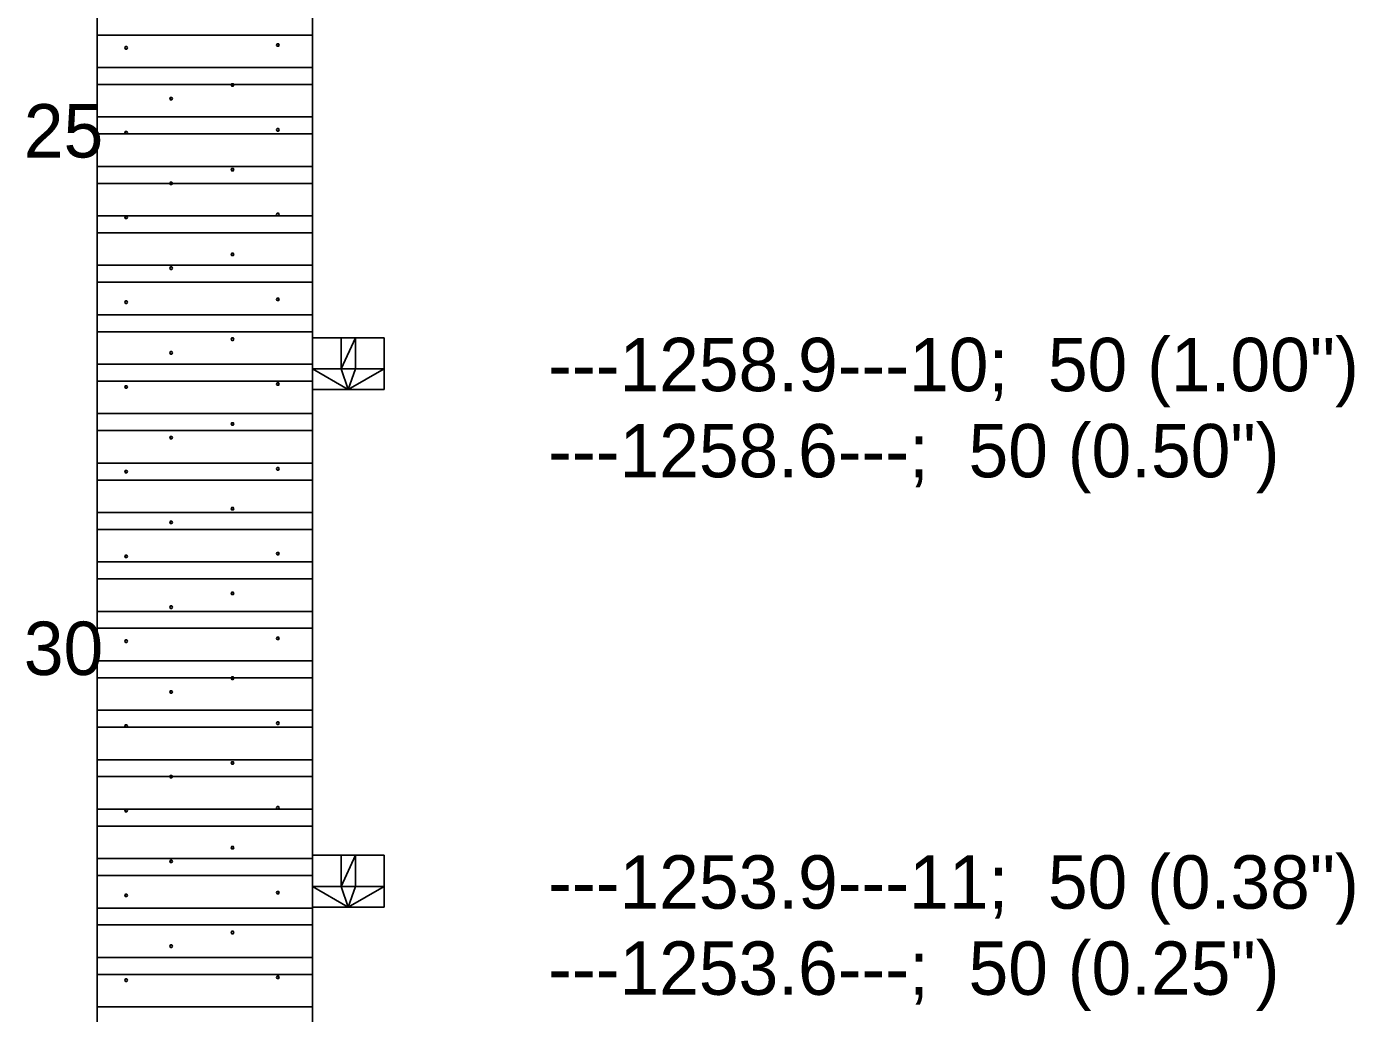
# Model space of a CAD drawing. Extents: x 2150148.6 to 2150220.1, y 143803.7 to 143875.1.
# Drawn here: x 2150191.796 to 2150194.882, y 143819.958 to 143822.25 of the extents above; entities that cross this region are included whole.
import ezdxf

# ---------------------------------------------------------------- set-up
doc = ezdxf.new("R2010")
doc.units = 0
doc.layers.add('Default', color=7, linetype='Continuous')

msp = doc.modelspace()

# ---------------------------------------------------------------- linework, layer by layer
at = {"layer": 'Default'}
for points in [[(2150191.9604, 143828.0174), (2150191.9604, 143817.9213)], [(2150192.4604, 143828.0174), (2150192.4604, 143817.9213)], [(2150191.9604, 143822.2303), (2150192.4604, 143822.2303)], [(2150192.0308, 143822.2005), (2150192.0292, 143822.2033), (2150192.0259, 143822.2033), (2150192.0243, 143822.2005), (2150192.0259, 143822.1976), (2150192.0292, 143822.1976), (2150192.0308, 143822.2005)], [(2150192.3836, 143822.207), (2150192.3819, 143822.2099), (2150192.3787, 143822.2099), (2150192.377, 143822.207), (2150192.3787, 143822.2041), (2150192.3819, 143822.2041), (2150192.3836, 143822.207)], [(2150191.9604, 143822.1548), (2150192.4604, 143822.1548)], [(2150191.9604, 143822.1154), (2150192.4604, 143822.1154)], [(2150192.2781, 143822.1144), (2150192.2764, 143822.1173), (2150192.2731, 143822.1173), (2150192.2715, 143822.1144), (2150192.2731, 143822.1116), (2150192.2764, 143822.1116), (2150192.2781, 143822.1144)], [(2150192.1355, 143822.0826), (2150192.1338, 143822.0854), (2150192.1306, 143822.0854), (2150192.1289, 143822.0826), (2150192.1306, 143822.0797), (2150192.1338, 143822.0797), (2150192.1355, 143822.0826)], [(2150191.9604, 143822.04), (2150192.4604, 143822.04)], [(2150192.0308, 143822.0036), (2150192.0292, 143822.0064), (2150192.0259, 143822.0064), (2150192.0243, 143822.0036), (2150192.0259, 143822.0007), (2150192.0292, 143822.0007), (2150192.0308, 143822.0036)], [(2150192.3836, 143822.0101), (2150192.3819, 143822.013), (2150192.3787, 143822.013), (2150192.377, 143822.0101), (2150192.3787, 143822.0073), (2150192.3819, 143822.0073), (2150192.3836, 143822.0101)], [(2150191.9604, 143822.0006), (2150192.4604, 143822.0006)], [(2150191.9604, 143821.9251), (2150192.4604, 143821.9251)], [(2150192.2781, 143821.9176), (2150192.2764, 143821.9204), (2150192.2731, 143821.9204), (2150192.2715, 143821.9176), (2150192.2731, 143821.9148), (2150192.2764, 143821.9148), (2150192.2781, 143821.9176)], [(2150191.9604, 143821.8858), (2150192.4604, 143821.8858)], [(2150192.1355, 143821.8857), (2150192.1338, 143821.8886), (2150192.1306, 143821.8886), (2150192.1289, 143821.8858), (2150192.1306, 143821.8829), (2150192.1338, 143821.8829), (2150192.1355, 143821.8857)], [(2150191.9604, 143821.8103), (2150192.4604, 143821.8103)], [(2150192.0308, 143821.8068), (2150192.0292, 143821.8096), (2150192.0259, 143821.8096), (2150192.0243, 143821.8068), (2150192.0259, 143821.8039), (2150192.0292, 143821.8039), (2150192.0308, 143821.8068)], [(2150192.3836, 143821.8133), (2150192.3819, 143821.8162), (2150192.3787, 143821.8162), (2150192.377, 143821.8133), (2150192.3787, 143821.8104), (2150192.3819, 143821.8104), (2150192.3836, 143821.8133)], [(2150191.9604, 143821.7709), (2150192.4604, 143821.7709)], [(2150191.9604, 143821.6955), (2150192.4604, 143821.6955)], [(2150192.2781, 143821.7207), (2150192.2764, 143821.7236), (2150192.2731, 143821.7236), (2150192.2715, 143821.7207), (2150192.2731, 143821.7179), (2150192.2764, 143821.7179), (2150192.2781, 143821.7207)], [(2150192.1355, 143821.6889), (2150192.1338, 143821.6917), (2150192.1306, 143821.6917), (2150192.1289, 143821.6889), (2150192.1306, 143821.686), (2150192.1338, 143821.686), (2150192.1355, 143821.6889)], [(2150191.9604, 143821.6561), (2150192.4604, 143821.6561)], [(2150192.0308, 143821.6099), (2150192.0292, 143821.6127), (2150192.0259, 143821.6127), (2150192.0243, 143821.6099), (2150192.0259, 143821.607), (2150192.0292, 143821.607), (2150192.0308, 143821.6099)], [(2150192.3836, 143821.6164), (2150192.3819, 143821.6193), (2150192.3787, 143821.6193), (2150192.377, 143821.6164), (2150192.3787, 143821.6136), (2150192.3819, 143821.6136), (2150192.3836, 143821.6164)], [(2150191.9604, 143821.5807), (2150192.4604, 143821.5807)], [(2150191.9604, 143821.5413), (2150192.4604, 143821.5413)], [(2150192.2781, 143821.5239), (2150192.2764, 143821.5267), (2150192.2731, 143821.5267), (2150192.2715, 143821.5239), (2150192.2731, 143821.5211), (2150192.2764, 143821.5211), (2150192.2781, 143821.5239)], [(2150192.4604, 143821.527), (2150192.6271, 143821.527)], [(2150192.6271, 143821.4068), (2150192.6271, 143821.527)], [(2150192.1355, 143821.492), (2150192.1338, 143821.4949), (2150192.1306, 143821.4949), (2150192.1289, 143821.4921), (2150192.1306, 143821.4892), (2150192.1338, 143821.4892), (2150192.1355, 143821.492)], [(2150191.9604, 143821.4658), (2150192.4604, 143821.4658)], [(2150191.9604, 143821.4265), (2150192.4604, 143821.4265)], [(2150192.3836, 143821.4196), (2150192.3819, 143821.4225), (2150192.3787, 143821.4225), (2150192.377, 143821.4196), (2150192.3787, 143821.4167), (2150192.3819, 143821.4167), (2150192.3836, 143821.4196)], [(2150192.0308, 143821.4131), (2150192.0292, 143821.4159), (2150192.0259, 143821.4159), (2150192.0243, 143821.4131), (2150192.0259, 143821.4102), (2150192.0292, 143821.4102), (2150192.0308, 143821.4131)], [(2150192.4604, 143821.4068), (2150192.6271, 143821.4068)], [(2150191.9604, 143821.351), (2150192.4604, 143821.351)], [(2150192.2781, 143821.327), (2150192.2764, 143821.3299), (2150192.2731, 143821.3299), (2150192.2715, 143821.327), (2150192.2731, 143821.3242), (2150192.2764, 143821.3242), (2150192.2781, 143821.327)], [(2150191.9604, 143821.3116), (2150192.4604, 143821.3116)], [(2150192.1355, 143821.2952), (2150192.1338, 143821.298), (2150192.1306, 143821.298), (2150192.1289, 143821.2952), (2150192.1306, 143821.2923), (2150192.1338, 143821.2923), (2150192.1355, 143821.2952)], [(2150191.9604, 143821.2362), (2150192.4604, 143821.2362)], [(2150192.0308, 143821.2162), (2150192.0292, 143821.219), (2150192.0259, 143821.219), (2150192.0243, 143821.2162), (2150192.0259, 143821.2133), (2150192.0292, 143821.2133), (2150192.0308, 143821.2162)], [(2150192.3836, 143821.2227), (2150192.3819, 143821.2256), (2150192.3787, 143821.2256), (2150192.377, 143821.2227), (2150192.3787, 143821.2199), (2150192.3819, 143821.2199), (2150192.3836, 143821.2227)], [(2150191.9604, 143821.1968), (2150192.4604, 143821.1968)], [(2150191.9604, 143821.1213), (2150192.4604, 143821.1213)], [(2150192.2781, 143821.1302), (2150192.2764, 143821.133), (2150192.2731, 143821.133), (2150192.2715, 143821.1302), (2150192.2731, 143821.1274), (2150192.2764, 143821.1274), (2150192.2781, 143821.1302)], [(2150191.9604, 143821.082), (2150192.4604, 143821.082)], [(2150192.1355, 143821.0983), (2150192.1338, 143821.1012), (2150192.1306, 143821.1012), (2150192.1289, 143821.0984), (2150192.1306, 143821.0955), (2150192.1338, 143821.0955), (2150192.1355, 143821.0983)], [(2150192.0308, 143821.0194), (2150192.0292, 143821.0222), (2150192.0259, 143821.0222), (2150192.0243, 143821.0194), (2150192.0259, 143821.0165), (2150192.0292, 143821.0165), (2150192.0308, 143821.0194)], [(2150192.3836, 143821.0259), (2150192.3819, 143821.0288), (2150192.3787, 143821.0288), (2150192.377, 143821.0259), (2150192.3787, 143821.023), (2150192.3819, 143821.023), (2150192.3836, 143821.0259)], [(2150191.9604, 143821.0065), (2150192.4604, 143821.0065)], [(2150191.9604, 143820.9671), (2150192.4604, 143820.9671)], [(2150192.2781, 143820.9333), (2150192.2764, 143820.9362), (2150192.2731, 143820.9362), (2150192.2715, 143820.9333), (2150192.2731, 143820.9305), (2150192.2764, 143820.9305), (2150192.2781, 143820.9333)], [(2150192.1355, 143820.9015), (2150192.1338, 143820.9043), (2150192.1306, 143820.9043), (2150192.1289, 143820.9015), (2150192.1306, 143820.8986), (2150192.1338, 143820.8986), (2150192.1355, 143820.9015)], [(2150191.9604, 143820.8917), (2150192.4604, 143820.8917)], [(2150191.9604, 143820.8523), (2150192.4604, 143820.8523)], [(2150192.3836, 143820.829), (2150192.3819, 143820.8319), (2150192.3787, 143820.8319), (2150192.377, 143820.829), (2150192.3787, 143820.8262), (2150192.3819, 143820.8262), (2150192.3836, 143820.829)], [(2150192.0308, 143820.8225), (2150192.0292, 143820.8253), (2150192.0259, 143820.8253), (2150192.0243, 143820.8225), (2150192.0259, 143820.8196), (2150192.0292, 143820.8196), (2150192.0308, 143820.8225)], [(2150191.9604, 143820.7769), (2150192.4604, 143820.7769)], [(2150192.2781, 143820.7365), (2150192.2764, 143820.7393), (2150192.2731, 143820.7393), (2150192.2715, 143820.7365), (2150192.2731, 143820.7337), (2150192.2764, 143820.7337), (2150192.2781, 143820.7365)], [(2150191.9604, 143820.7375), (2150192.4604, 143820.7375)], [(2150192.1355, 143820.7046), (2150192.1338, 143820.7075), (2150192.1306, 143820.7075), (2150192.1289, 143820.7047), (2150192.1306, 143820.7018), (2150192.1338, 143820.7018), (2150192.1355, 143820.7046)], [(2150191.9604, 143820.662), (2150192.4604, 143820.662)], [(2150191.9604, 143820.6227), (2150192.4604, 143820.6227)], [(2150192.0308, 143820.6257), (2150192.0292, 143820.6285), (2150192.0259, 143820.6285), (2150192.0243, 143820.6257), (2150192.0259, 143820.6228), (2150192.0292, 143820.6228), (2150192.0308, 143820.6257)], [(2150192.3836, 143820.6322), (2150192.3819, 143820.6351), (2150192.3787, 143820.6351), (2150192.377, 143820.6322), (2150192.3787, 143820.6293), (2150192.3819, 143820.6293), (2150192.3836, 143820.6322)], [(2150191.9604, 143820.5472), (2150192.4604, 143820.5472)], [(2150192.2781, 143820.5396), (2150192.2764, 143820.5425), (2150192.2731, 143820.5425), (2150192.2715, 143820.5396), (2150192.2731, 143820.5368), (2150192.2764, 143820.5368), (2150192.2781, 143820.5396)], [(2150191.9604, 143820.5078), (2150192.4604, 143820.5078)], [(2150192.1355, 143820.5078), (2150192.1338, 143820.5106), (2150192.1306, 143820.5106), (2150192.1289, 143820.5078), (2150192.1306, 143820.5049), (2150192.1338, 143820.5049), (2150192.1355, 143820.5078)], [(2150191.9604, 143820.4324), (2150192.4604, 143820.4324)], [(2150192.0308, 143820.4288), (2150192.0292, 143820.4316), (2150192.0259, 143820.4316), (2150192.0243, 143820.4288), (2150192.0259, 143820.4259), (2150192.0292, 143820.4259), (2150192.0308, 143820.4288)], [(2150192.3836, 143820.4353), (2150192.3819, 143820.4382), (2150192.3787, 143820.4382), (2150192.377, 143820.4353), (2150192.3787, 143820.4325), (2150192.3819, 143820.4325), (2150192.3836, 143820.4353)], [(2150191.9604, 143820.393), (2150192.4604, 143820.393)], [(2150192.2781, 143820.3428), (2150192.2764, 143820.3456), (2150192.2731, 143820.3456), (2150192.2715, 143820.3428), (2150192.2731, 143820.34), (2150192.2764, 143820.34), (2150192.2781, 143820.3428)], [(2150191.9604, 143820.3175), (2150192.4604, 143820.3175)], [(2150192.1355, 143820.3109), (2150192.1338, 143820.3138), (2150192.1306, 143820.3138), (2150192.1289, 143820.311), (2150192.1306, 143820.3081), (2150192.1338, 143820.3081), (2150192.1355, 143820.3109)], [(2150192.4604, 143820.3251), (2150192.6271, 143820.3251)], [(2150192.6271, 143820.2049), (2150192.6271, 143820.3251)], [(2150191.9604, 143820.2782), (2150192.4604, 143820.2782)], [(2150192.0308, 143820.232), (2150192.0292, 143820.2348), (2150192.0259, 143820.2348), (2150192.0243, 143820.232), (2150192.0259, 143820.2291), (2150192.0292, 143820.2291), (2150192.0308, 143820.232)], [(2150192.3836, 143820.2385), (2150192.3819, 143820.2414), (2150192.3787, 143820.2414), (2150192.377, 143820.2385), (2150192.3787, 143820.2356), (2150192.3819, 143820.2356), (2150192.3836, 143820.2385)], [(2150191.9604, 143820.2027), (2150192.4604, 143820.2027)], [(2150192.4604, 143820.2049), (2150192.6271, 143820.2049)], [(2150191.9604, 143820.1633), (2150192.4604, 143820.1633)], [(2150192.2781, 143820.1459), (2150192.2764, 143820.1488), (2150192.2731, 143820.1488), (2150192.2715, 143820.1459), (2150192.2731, 143820.1431), (2150192.2764, 143820.1431), (2150192.2781, 143820.1459)], [(2150192.1355, 143820.1141), (2150192.1338, 143820.1169), (2150192.1306, 143820.1169), (2150192.1289, 143820.1141), (2150192.1306, 143820.1112), (2150192.1338, 143820.1112), (2150192.1355, 143820.1141)], [(2150191.9604, 143820.0879), (2150192.4604, 143820.0879)], [(2150191.9604, 143820.0485), (2150192.4604, 143820.0485)], [(2150192.0308, 143820.0351), (2150192.0292, 143820.0379), (2150192.0259, 143820.0379), (2150192.0243, 143820.0351), (2150192.0259, 143820.0322), (2150192.0292, 143820.0322), (2150192.0308, 143820.0351)], [(2150192.3836, 143820.0416), (2150192.3819, 143820.0445), (2150192.3787, 143820.0445), (2150192.377, 143820.0416), (2150192.3787, 143820.0388), (2150192.3819, 143820.0388), (2150192.3836, 143820.0416)], [(2150191.9604, 143819.973), (2150192.4604, 143819.973)]]:
    msp.add_lwpolyline(points, dxfattribs=at)
for points in [[(2150192.5271, 143821.4549), (2150192.5604, 143821.4549), (2150192.5604, 143821.527), (2150192.5271, 143821.4549)], [(2150192.5271, 143821.4549), (2150192.5604, 143821.527), (2150192.5271, 143821.527), (2150192.5271, 143821.4549)], [(2150192.5271, 143821.4549), (2150192.4604, 143821.4549), (2150192.5437, 143821.4068), (2150192.5271, 143821.4549)], [(2150192.5271, 143821.4549), (2150192.5437, 143821.4068), (2150192.5604, 143821.4549), (2150192.5271, 143821.4549)], [(2150192.5437, 143821.4068), (2150192.6271, 143821.4549), (2150192.5604, 143821.4549), (2150192.5437, 143821.4068)], [(2150192.5271, 143820.253), (2150192.5604, 143820.253), (2150192.5604, 143820.3251), (2150192.5271, 143820.253)], [(2150192.5271, 143820.253), (2150192.5604, 143820.3251), (2150192.5271, 143820.3251), (2150192.5271, 143820.253)], [(2150192.5271, 143820.253), (2150192.4604, 143820.253), (2150192.5437, 143820.2049), (2150192.5271, 143820.253)], [(2150192.5271, 143820.253), (2150192.5437, 143820.2049), (2150192.5604, 143820.253), (2150192.5271, 143820.253)], [(2150192.5437, 143820.2049), (2150192.6271, 143820.253), (2150192.5604, 143820.253), (2150192.5437, 143820.2049)]]:
    msp.add_lwpolyline(points, close=True, dxfattribs=at)

# ---------------------------------------------------------------- texts
for s, p in [('25', (2150191.79, 143821.9458)), ('---1258.9---10;  50 (1.00")', (2150193.0084, 143821.403)), ('---1258.6---;  50 (0.50")', (2150193.0084, 143821.203)), ('30', (2150191.79, 143820.7439)), ('---1253.9---11;  50 (0.38")', (2150193.0084, 143820.2011)), ('---1253.6---;  50 (0.25")', (2150193.0084, 143820.0011))]:
    msp.add_text(s, height=0.124, dxfattribs=at).set_placement(p)

doc.saveas('drawing.dxf')
